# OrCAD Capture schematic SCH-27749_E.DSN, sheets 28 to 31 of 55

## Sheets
28 T4240 DDR Controller #1: size C
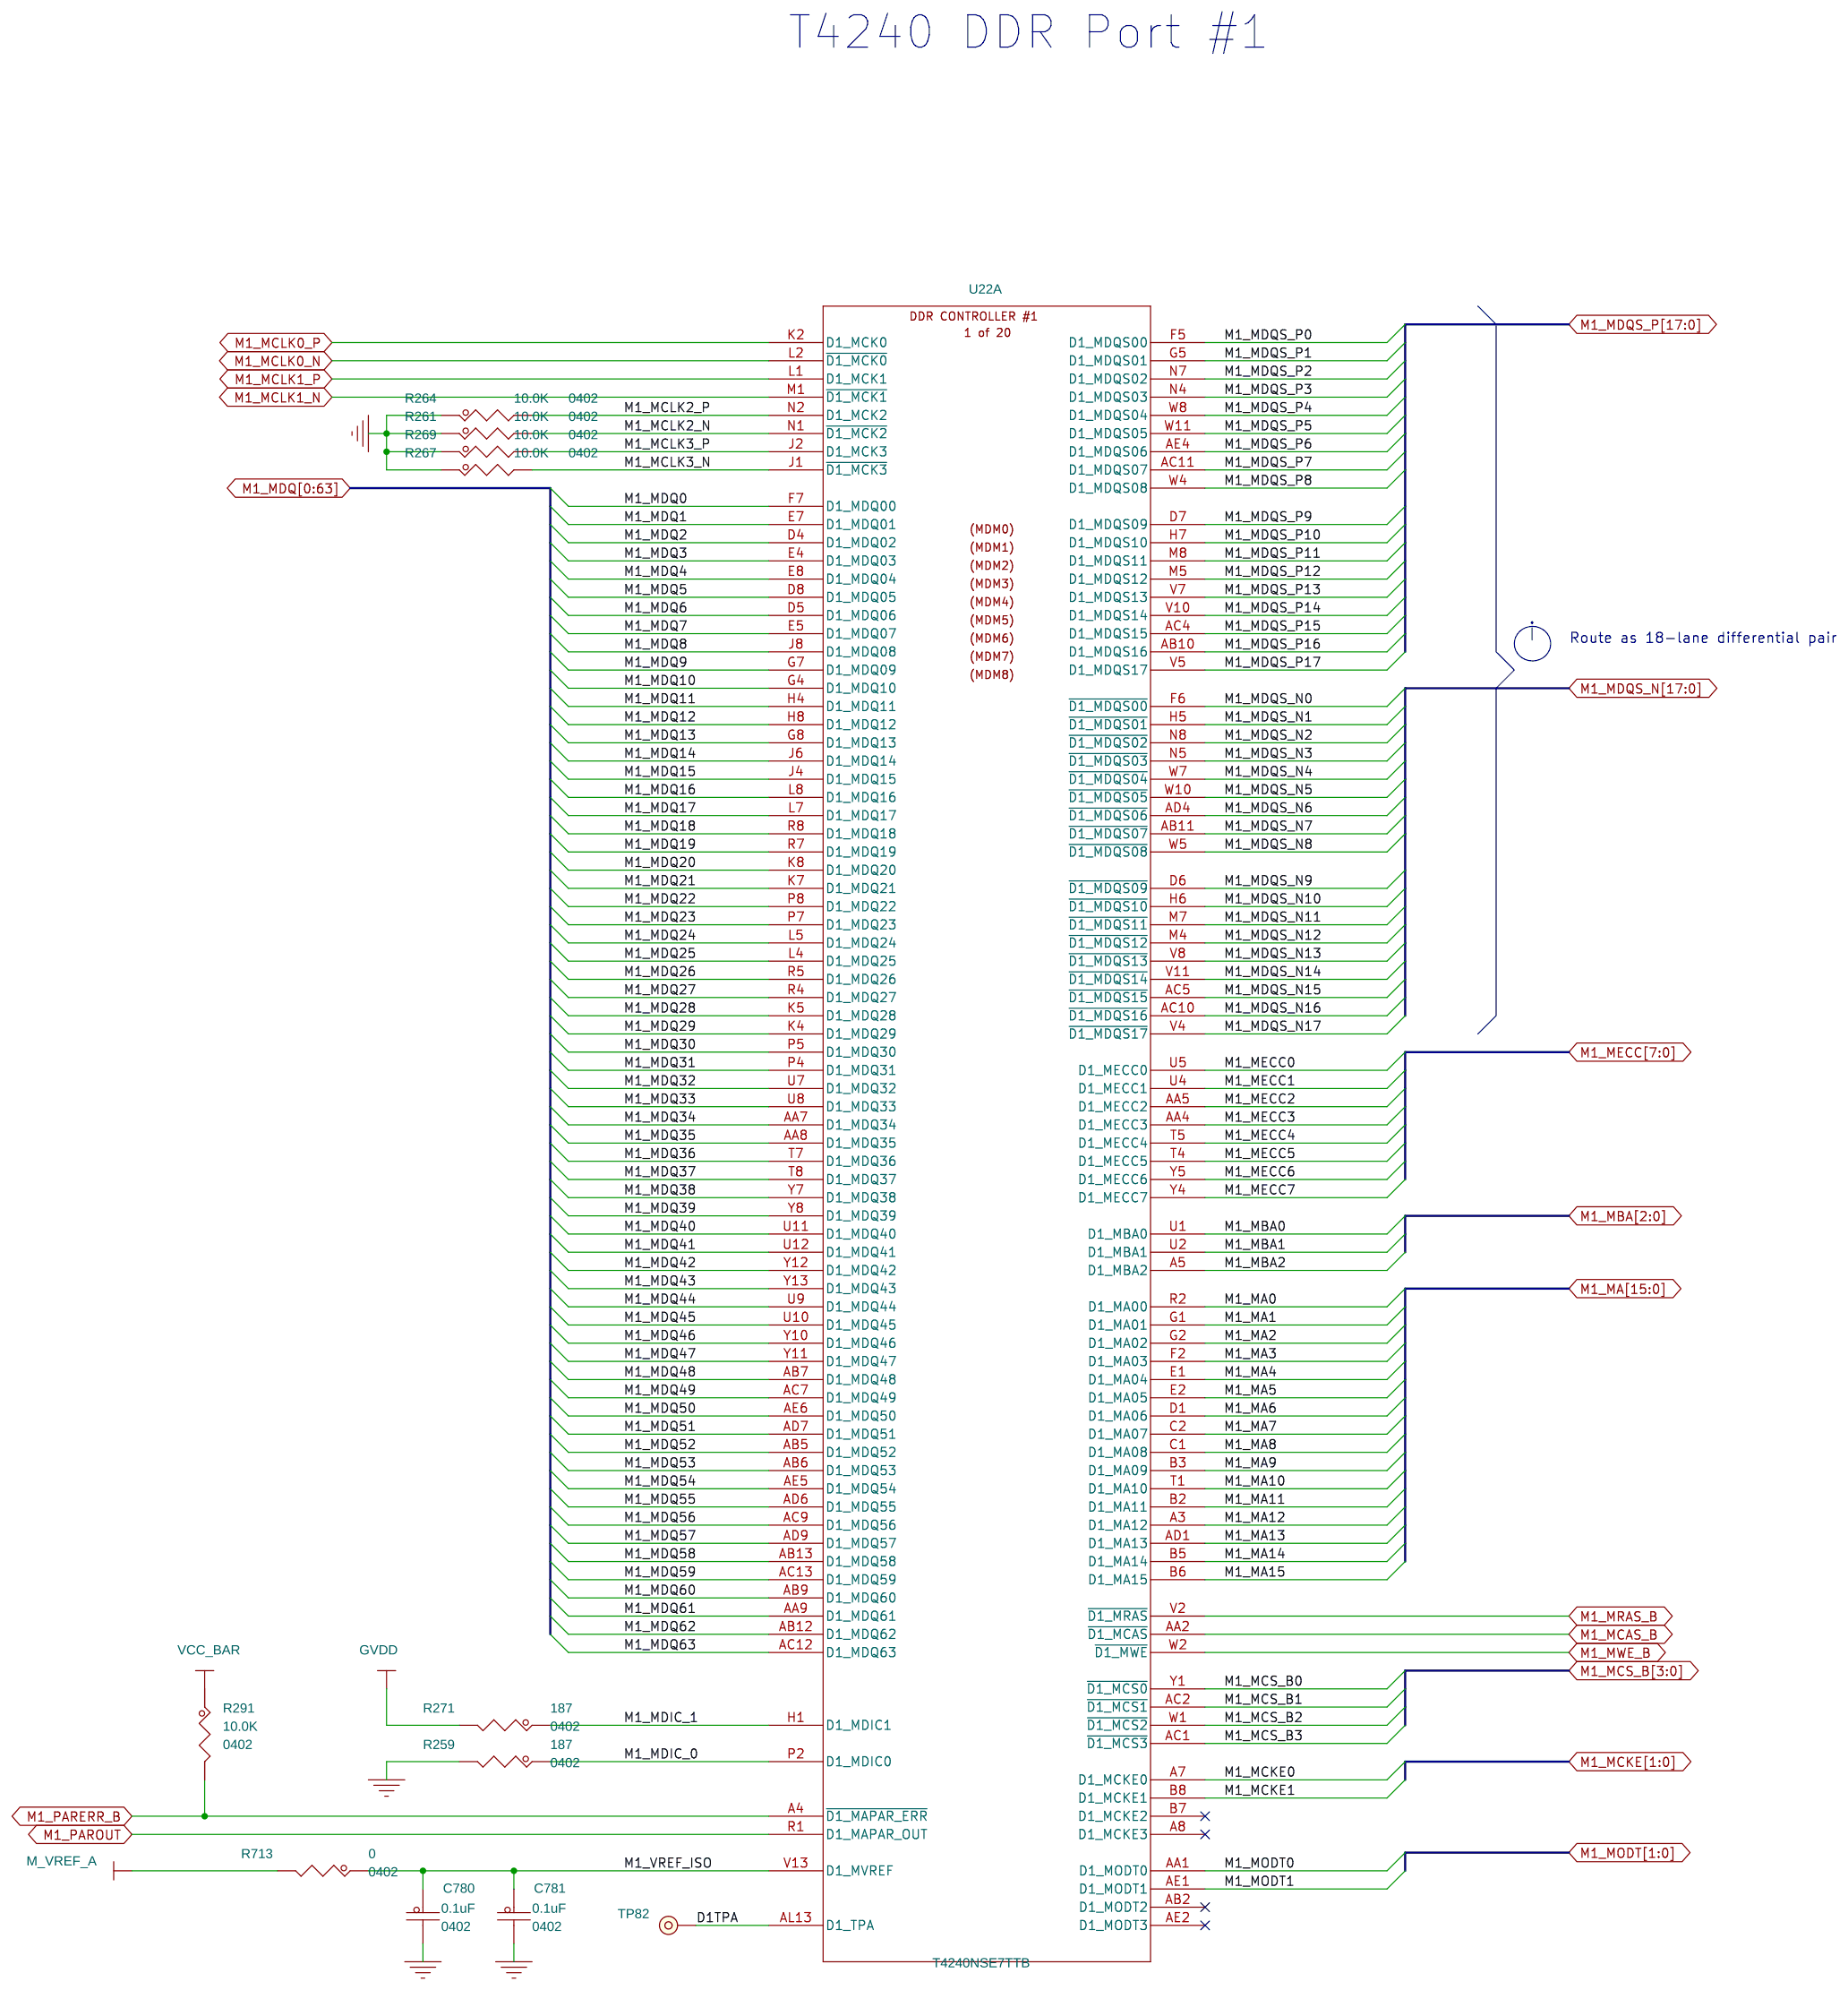
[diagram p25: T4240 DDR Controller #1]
29 T4240 DDR Controller #2: size C
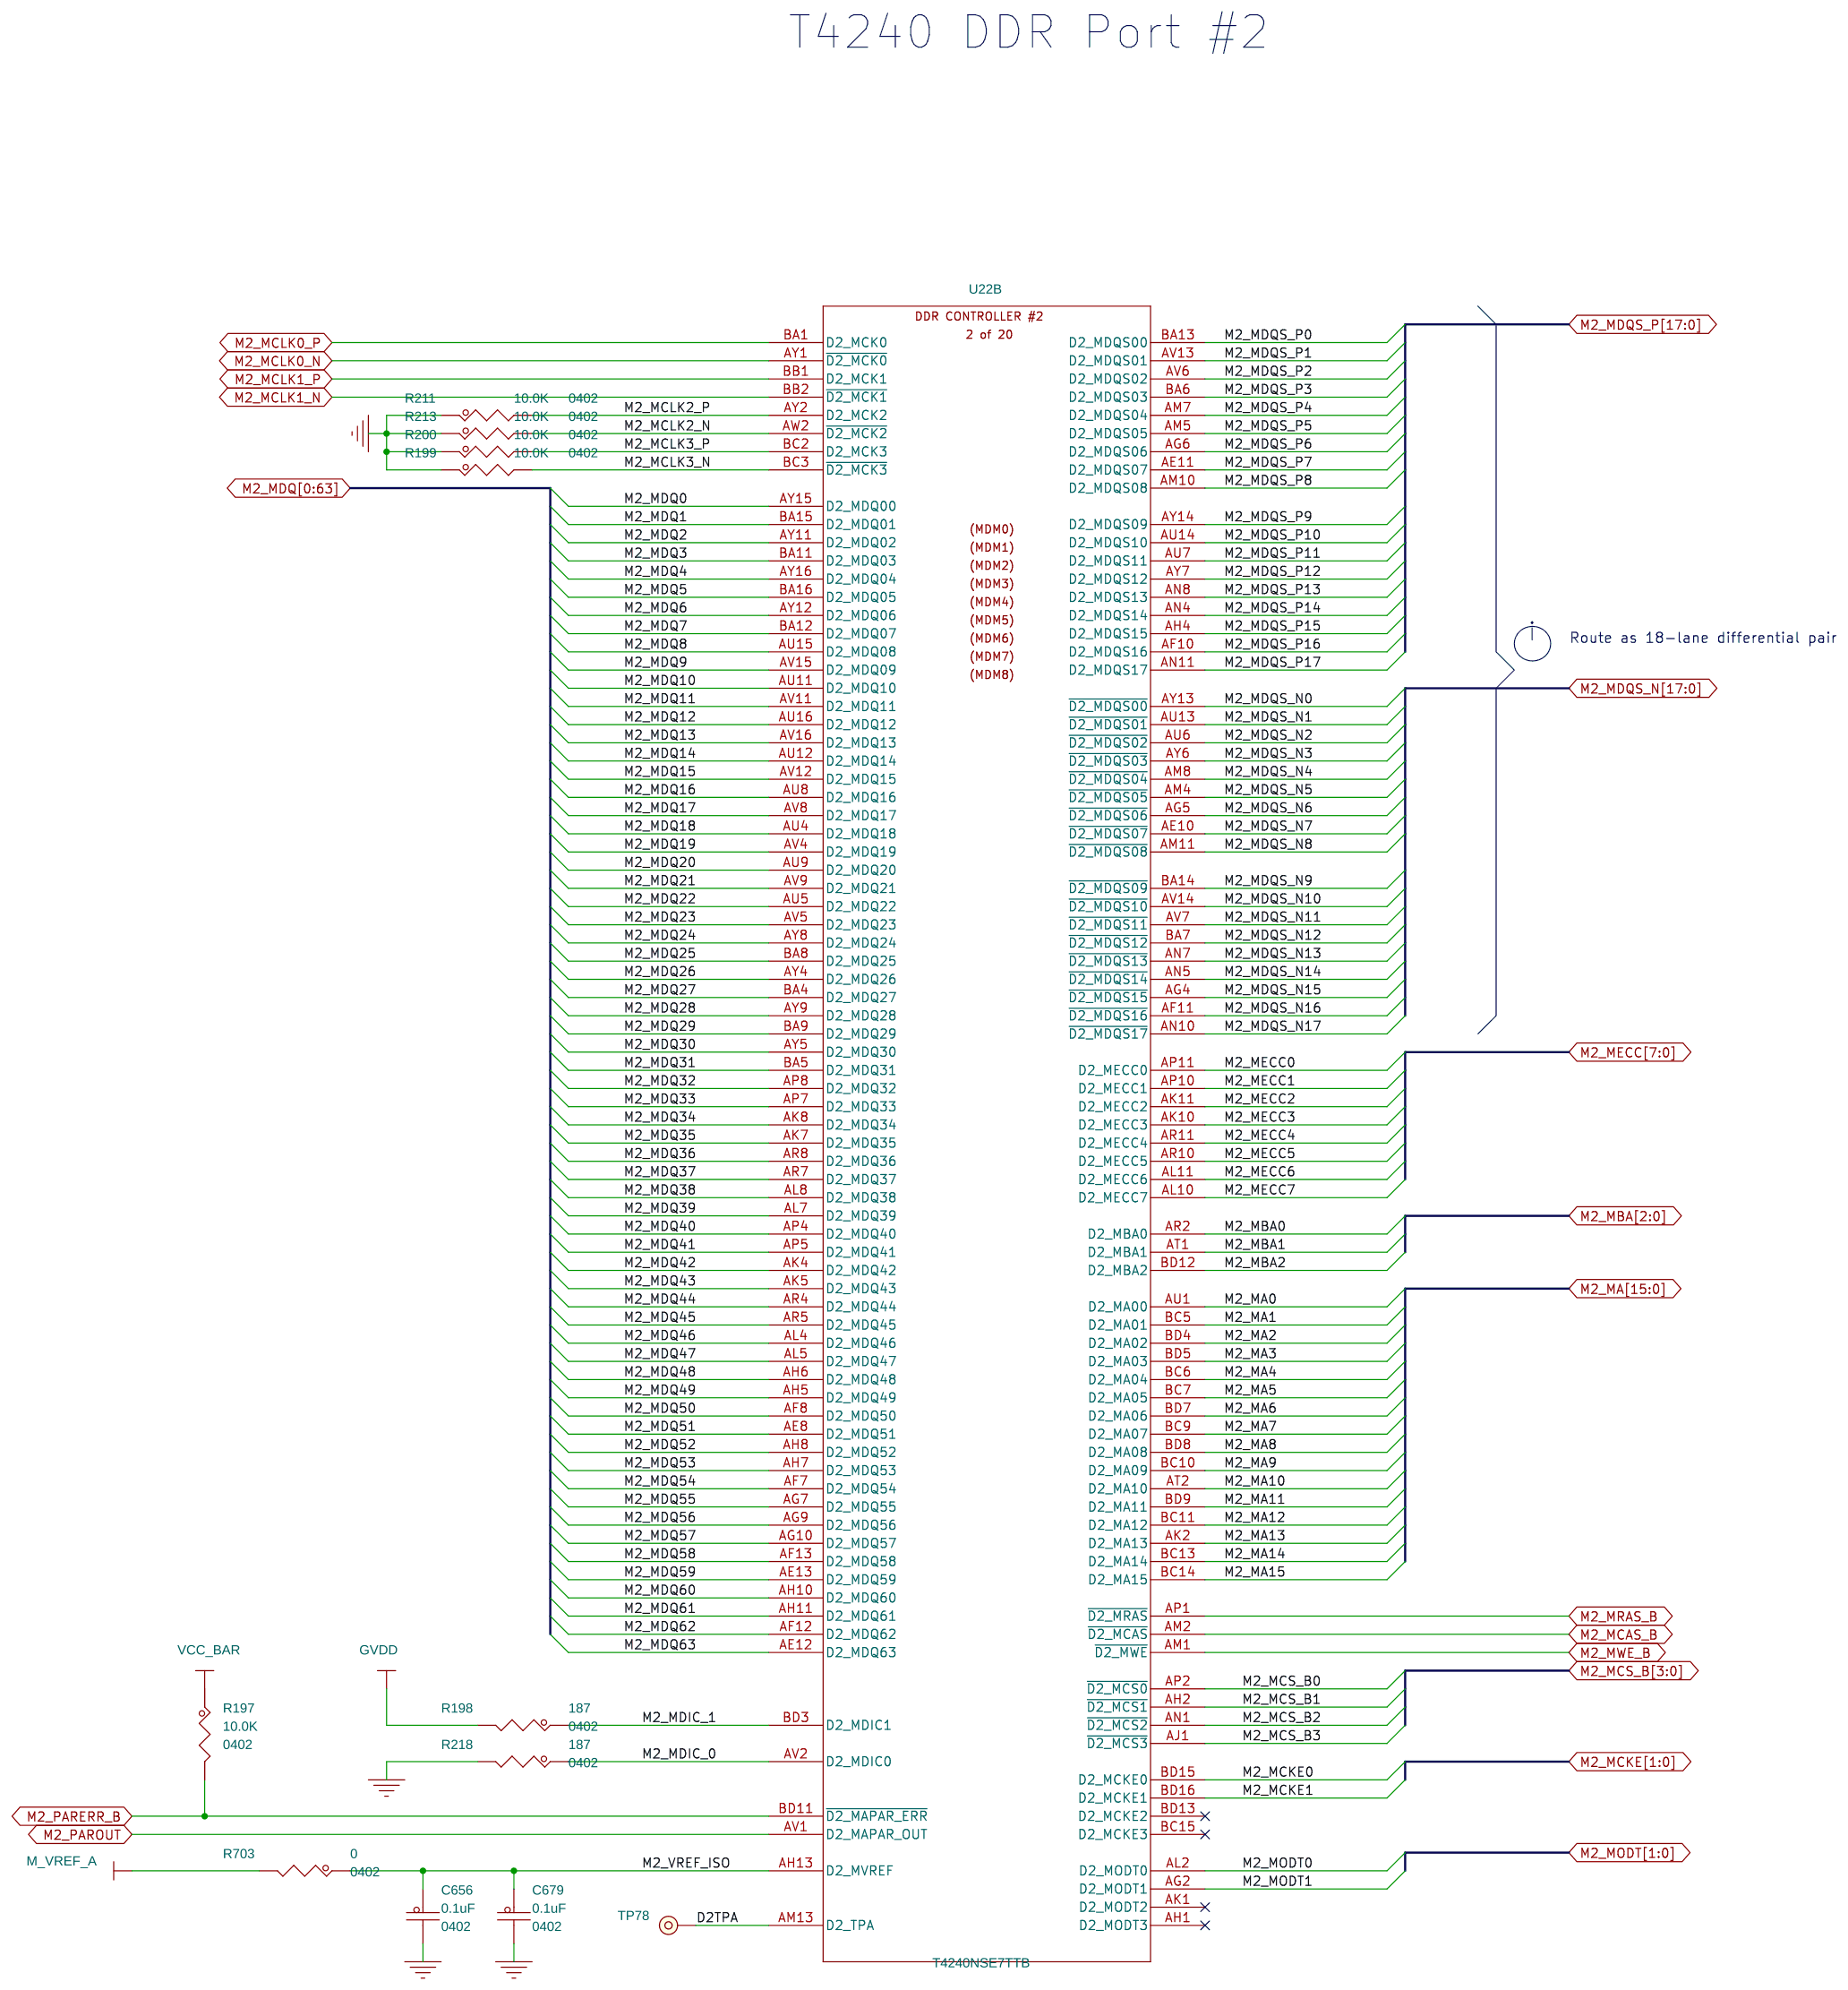
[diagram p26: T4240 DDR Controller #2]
30 T4240 DDR Controller #3: size C
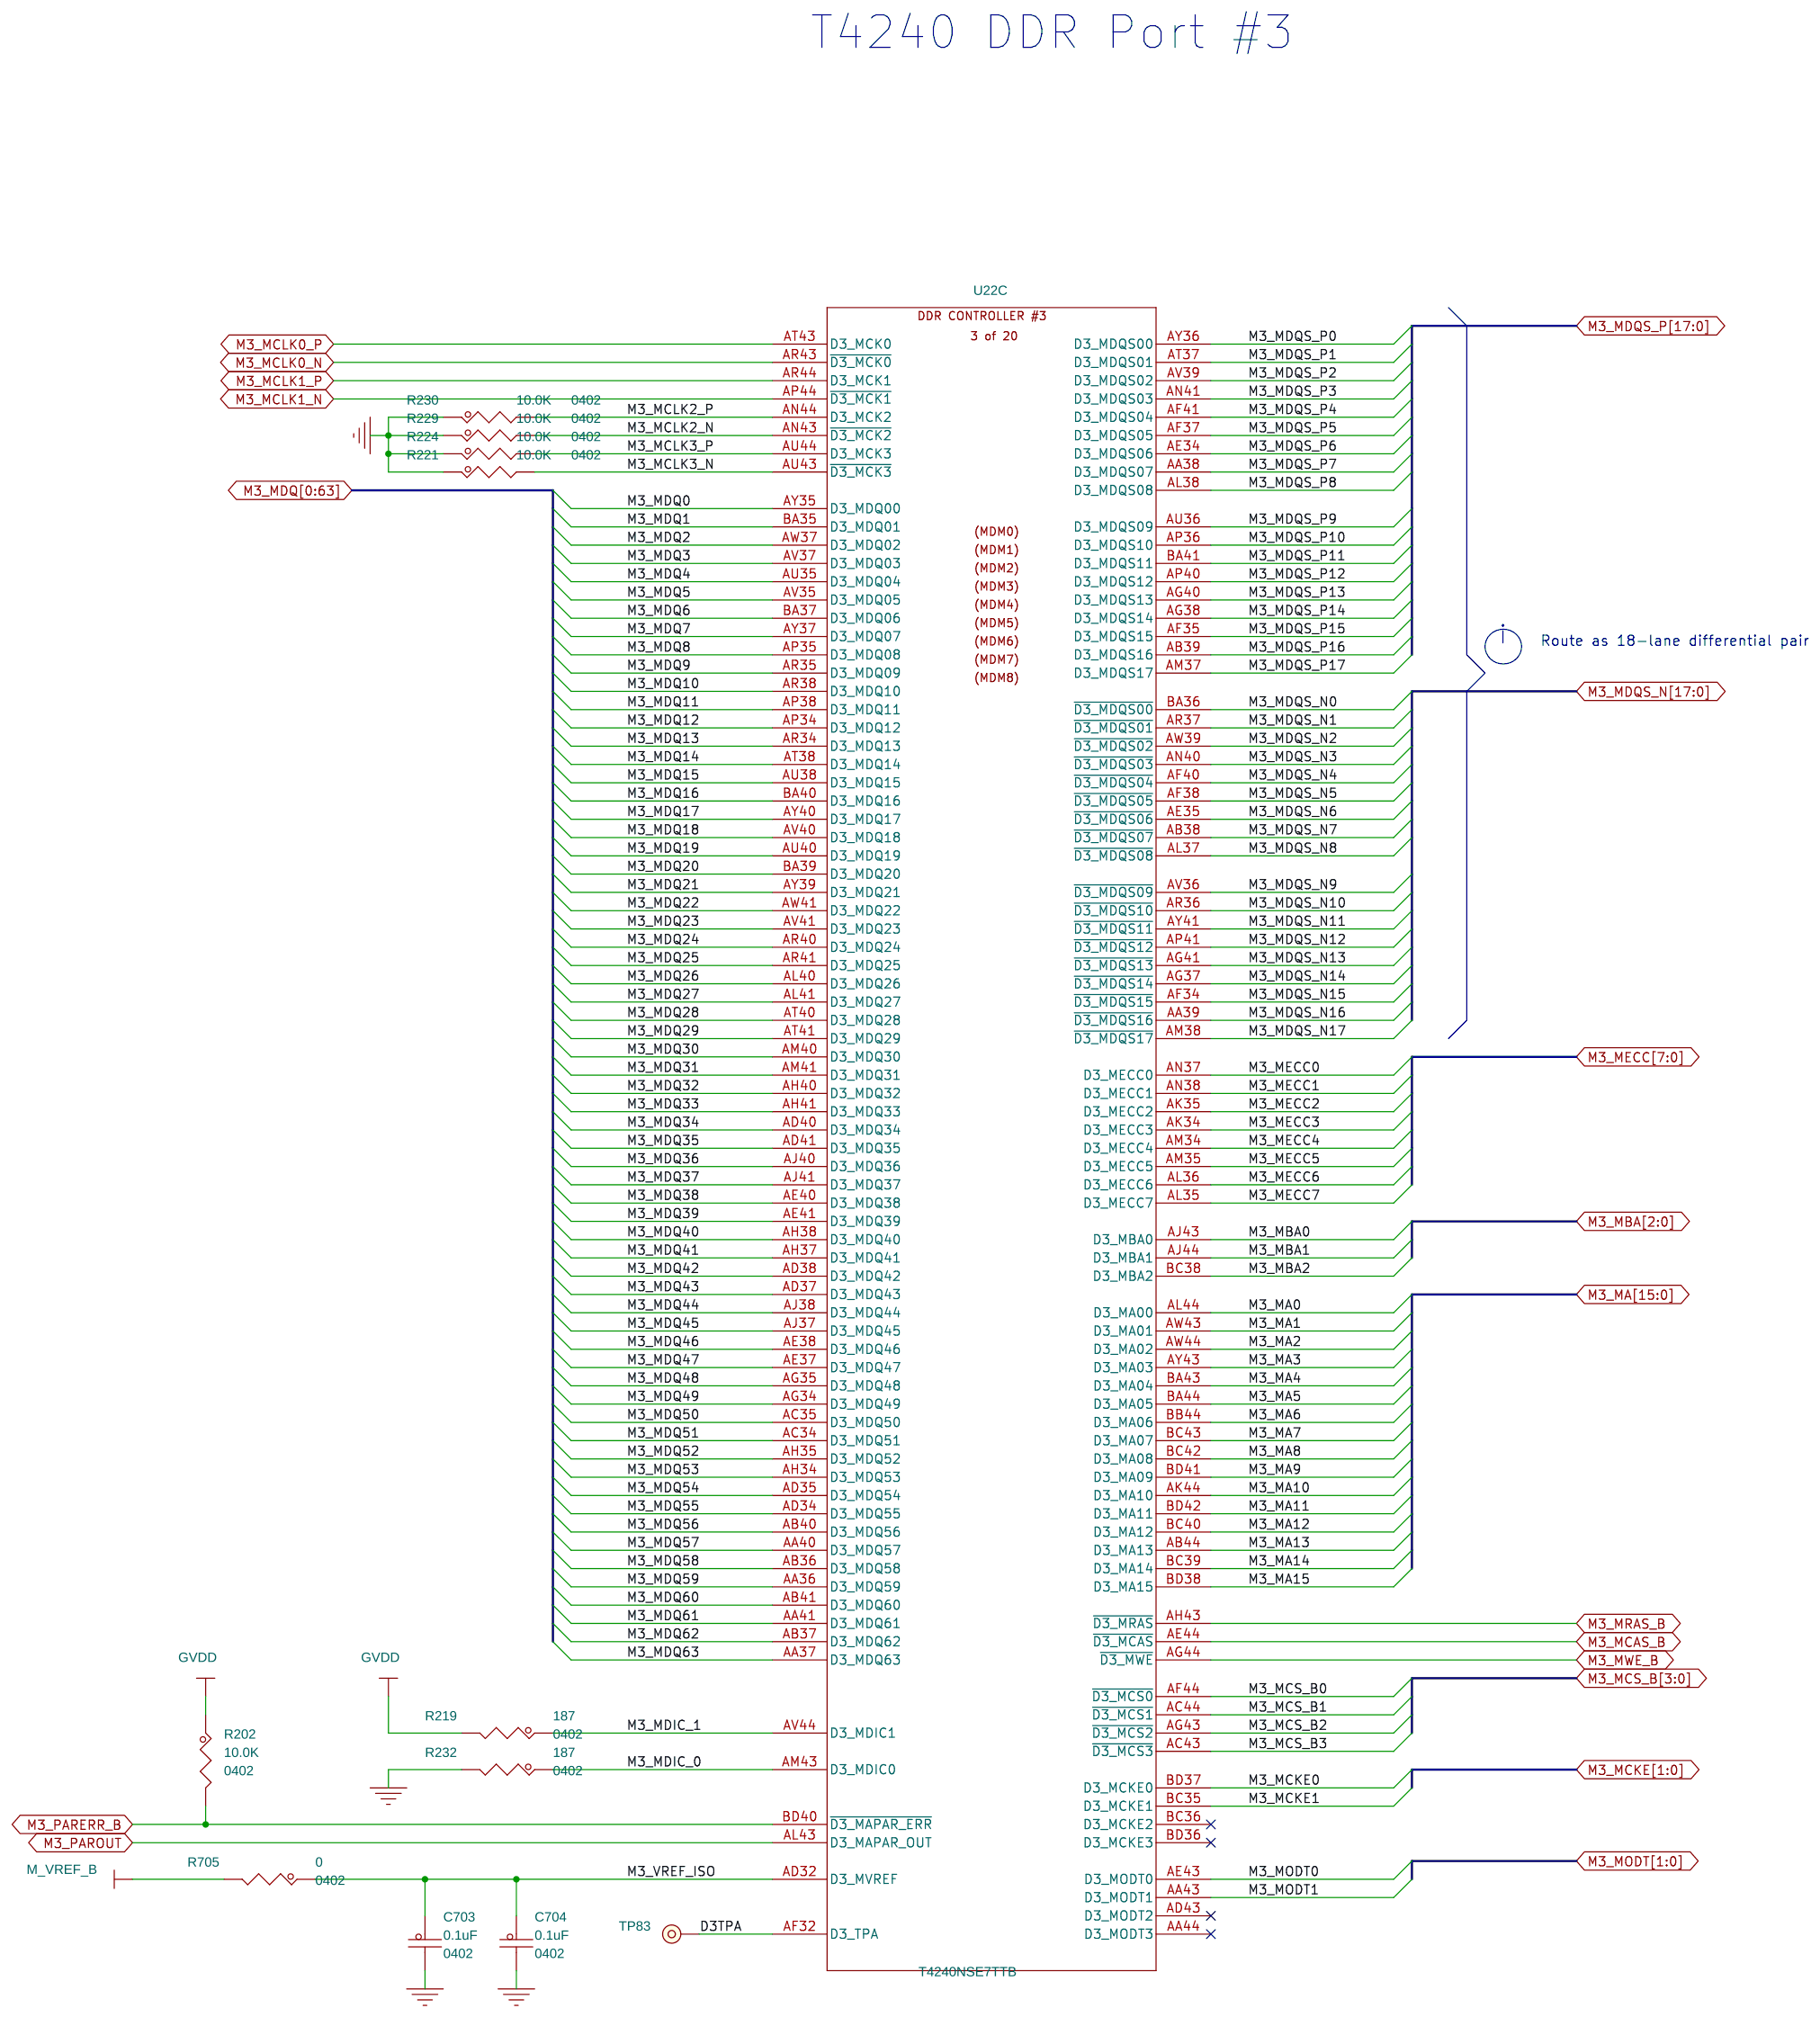
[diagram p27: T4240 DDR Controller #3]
31 DDR #1 DIMM: size C
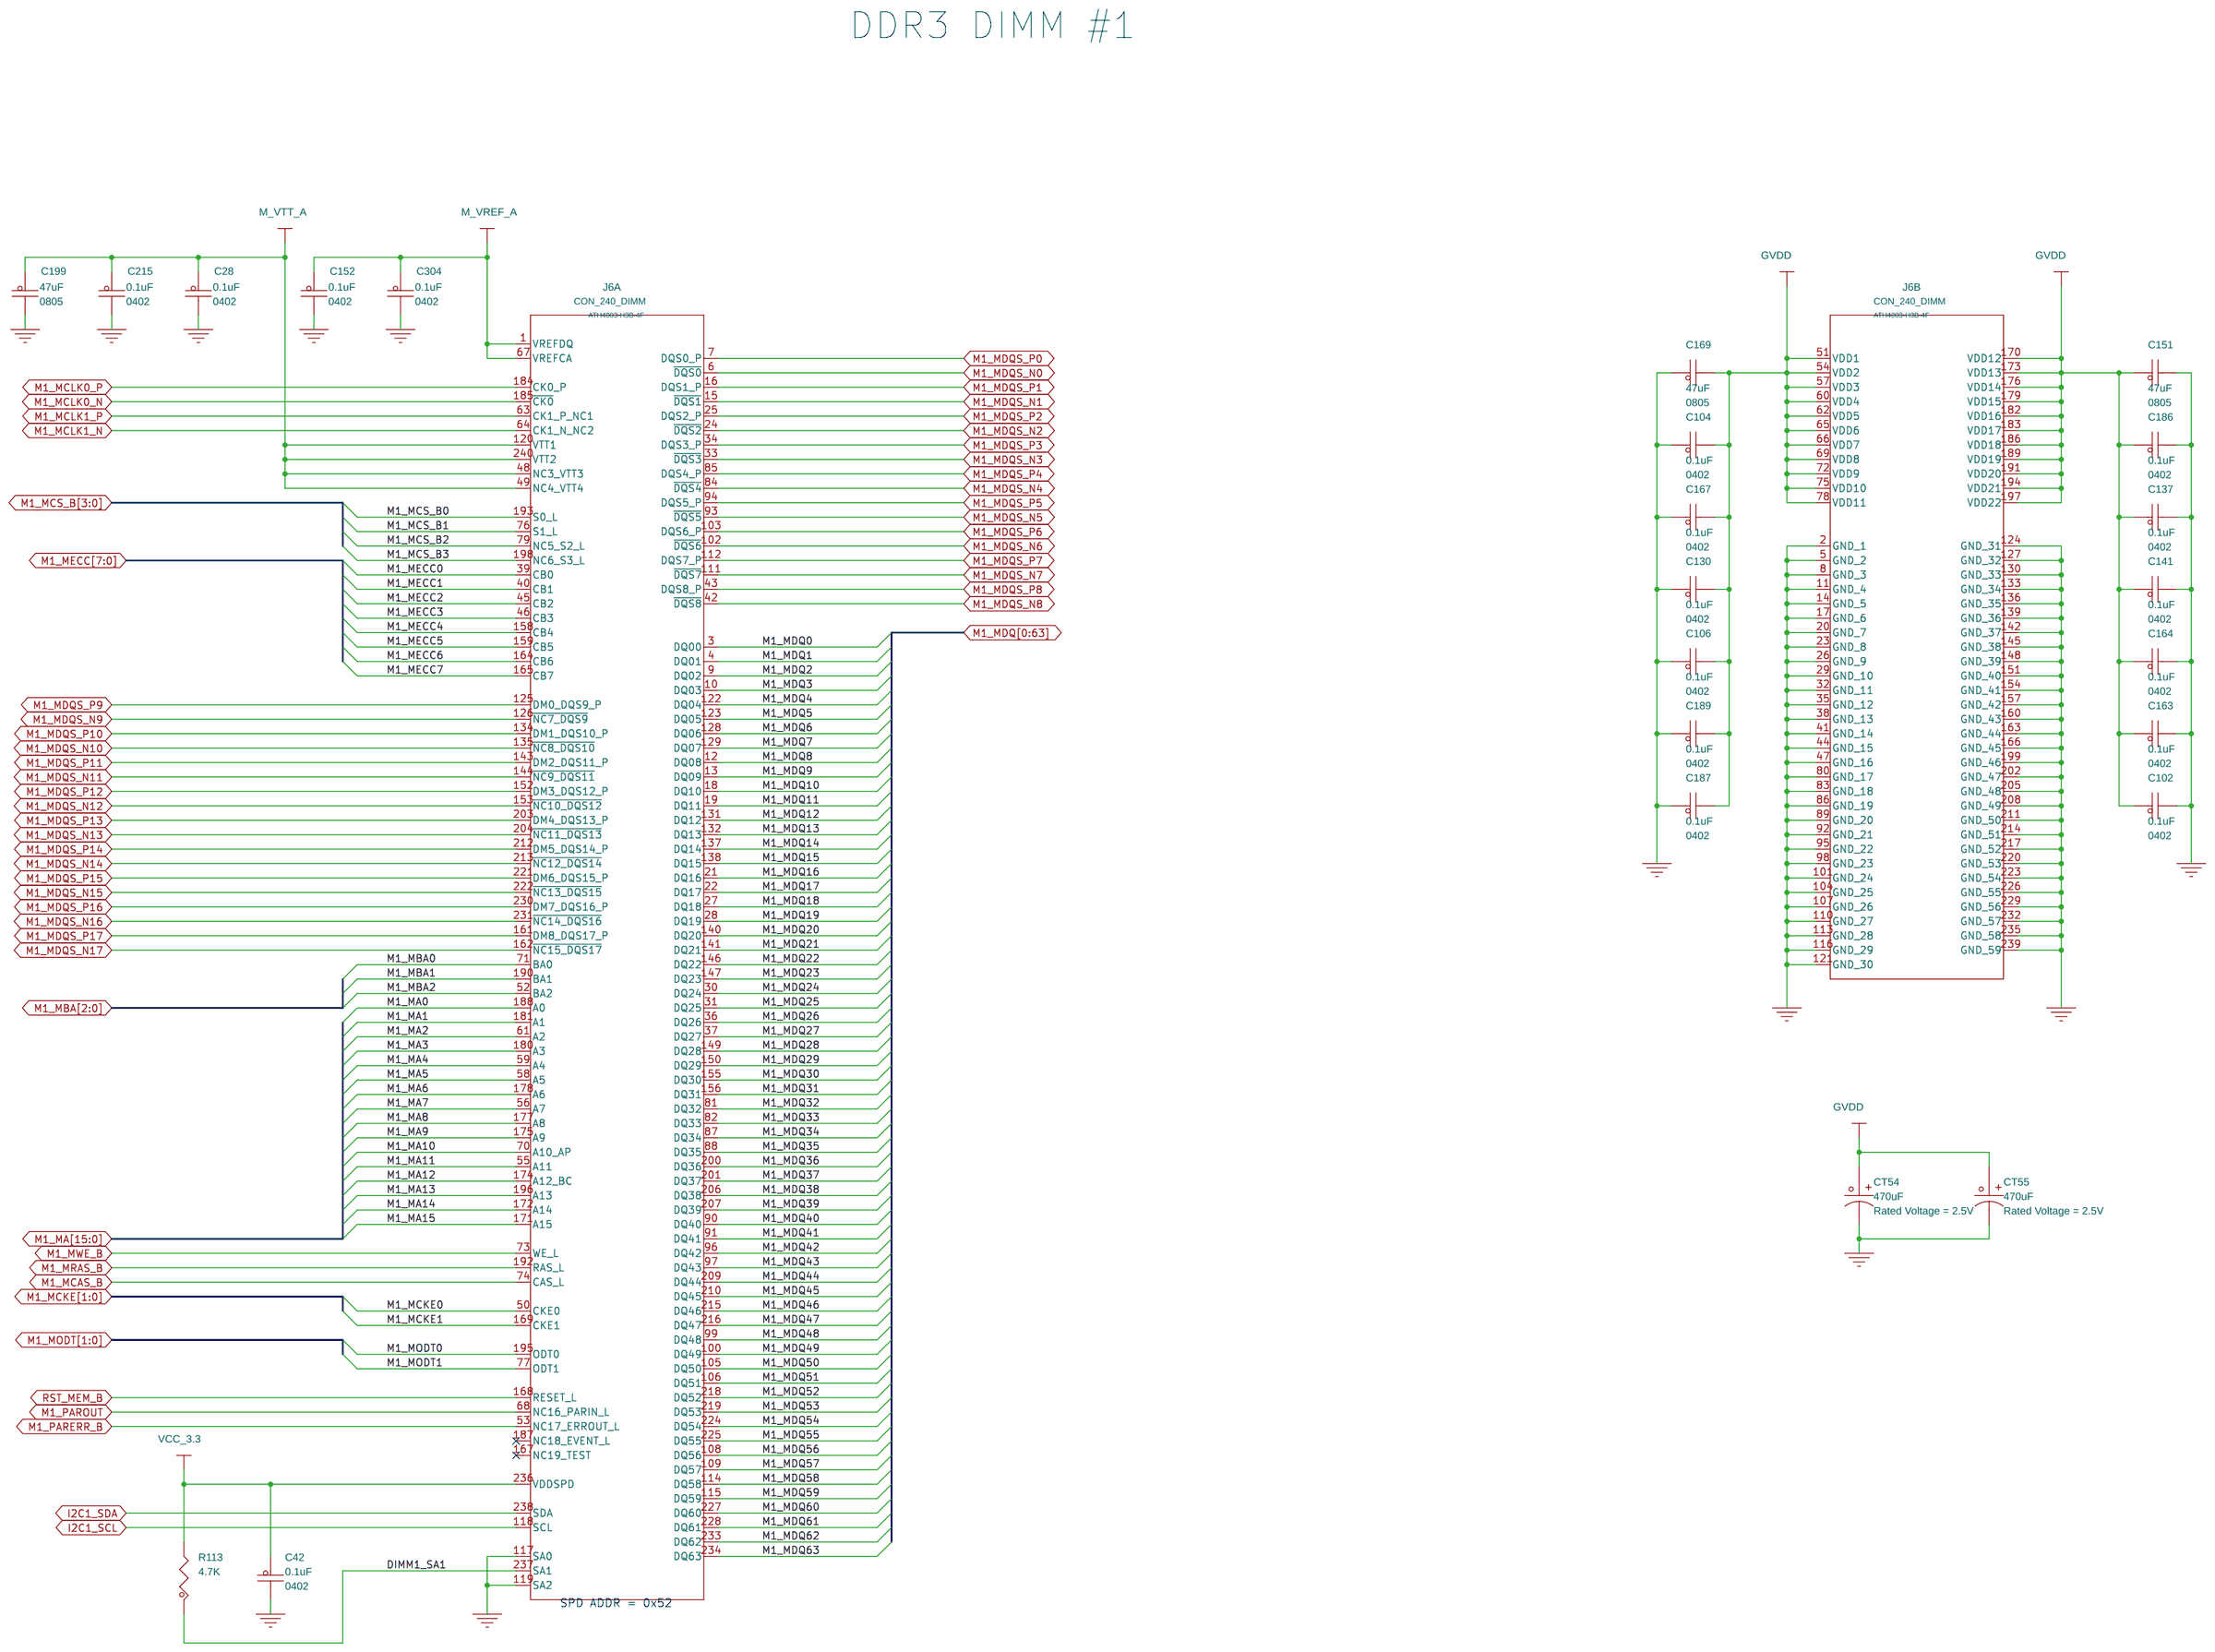
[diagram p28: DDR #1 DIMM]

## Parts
sheet DDR #1 DIMM
C28  0.1uF  [CC0402_HD]
C42  0.1uF  [CC0402_HD]
C102  0.1uF  [CC0402_HD]
C104  0.1uF  [CC0402_HD]
C106  0.1uF  [CC0402_HD]
C130  0.1uF  [CC0402_HD]
C137  0.1uF  [CC0402_HD]
C141  0.1uF  [CC0402_HD]
C151  47uF  [CC0805_OV]
C152  0.1uF  [CC0402_HD]
C163  0.1uF  [CC0402_HD]
C164  0.1uF  [CC0402_HD]
C167  0.1uF  [CC0402_HD]
C169  47uF  [CC0805_OV]
C186  0.1uF  [CC0402_HD]
C187  0.1uF  [CC0402_HD]
C189  0.1uF  [CC0402_HD]
C199  47uF  [CC0805_OV]
C215  0.1uF  [CC0402_HD]
C304  0.1uF  [CC0402_HD]
CT54  470uF  [CC7343A]
CT55  470uF  [CC7343A]
J6  CON_240_DIMM  [CON_240_DDR3_DIMM_SKT]  (sections A,B)
R113  4.7K  [RC0402_25]
sheet T4240 DDR Controller #1
C780  0.1uF  [CC0402_HD]
C781  0.1uF  [CC0402_HD]
R259  187  [RC0402_25]
R261  10.0K  [RC0402_25]
R264  10.0K  [RC0402_25]
R267  10.0K  [RC0402_25]
R269  10.0K  [RC0402_25]
R271  187  [RC0402_25]
R291  10.0K  [RC0402_25]
R713  0  [RC0402_25]
TP82  TPAD_020  [tpad_020_top]
sheet T4240 DDR Controller #2
C656  0.1uF  [CC0402_HD]
C679  0.1uF  [CC0402_HD]
R197  10.0K  [RC0402_25]
R198  187  [RC0402_25]
R199  10.0K  [RC0402_25]
R200  10.0K  [RC0402_25]
R211  10.0K  [RC0402_25]
R213  10.0K  [RC0402_25]
R218  187  [RC0402_25]
R703  0  [RC0402_25]
TP78  TPAD_020  [tpad_020_top]
U22  T4240NSE7TTB  [BGA1932_1MM_45X45MM]  (sections A,B,C,D,E,F,G,H,I,J,K,L,M,N,O,P,Q,R,S,T)
sheet T4240 DDR Controller #3
C703  0.1uF  [CC0402_HD]
C704  0.1uF  [CC0402_HD]
R202  10.0K  [RC0402_25]
R219  187  [RC0402_25]
R221  10.0K  [RC0402_25]
R224  10.0K  [RC0402_25]
R229  10.0K  [RC0402_25]
R230  10.0K  [RC0402_25]
R232  187  [RC0402_25]
R705  0  [RC0402_25]
TP83  TPAD_020  [tpad_020_top]

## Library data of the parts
C28 C42 C102 C104 C106 C130 C137 C141 C152 C163 C164 C167 C186 C187 C189 C215 C304 C656 C679 C703 C704 C780 C781 = CAP_NP: CAP CER 0.1uF 16V 10% X7R AEC-Q200 0402; AGILE_PN: 150-79025; CAD_APPROVED: Yes; FPLIST: CC0402_25,CC0402_HD,0402_CC,capc0402_l; HEIGHT: 0.55MM; MFG_NAME01: MURATA; MFG_PN01: GCM155R71C104KA55D; Package: 0402; Package Size: 0402; Package Type: ø180mm Reel PAPER; Part Number: 4CC104B163X00; Product Name: (H)MLCC 0.1uF/16V +-10% 0402 X7R; ROHS: Yes; Rated Voltage: 16V; Temp Range: -55C to +125C; Tolerance: 10%
C151 C169 C199 = CAP_NP: CAP CER 47uF 6.3V 20% X5R AEC-Q200 0805; AGILE_PN: 150-80462; CAD_APPROVED: Yes; FPLIST: CC0805_OV,CC0805,0805_CC; HEIGHT: 1.45MM; MFG_NAME01: MURATA; MFG_PN01: GRT21BR60J476ME13L; Package: 0805; Package Size: 2x1.25MM; Package Type: 0805; Part Number: 4CC476D631X00; Product Name: (H)MLCC 47uF/6.3V +-20% 0805 X5R; ROHS: Yes; Rated Voltage: 6.3V; Temp Range: -55C to +85C; Tolerance: 20%
CT54 CT55 = CAP_POL: CAP TANT ESR=0.009 OHMS 470UF 2.5V 20% -- 7343-18; AGILE_PN: 150-78476; CAD_APPROVED: Yes; HEIGHT: 1.9MM; MFG_NAME01: SANYO; MFG_PN01: 2R5TPE470M9; Package: SMD; Part Number: 4CP477D021X00; Product Name: KO CAP 470uF/2.5V KEMET:T520V477M2R5ATE009; ROHS: Yes; Rated Voltage: 2.5V; Tolerance: 20%
J6 = DDR3_240P: CON 240 DIMM DDR3 1.5V SKT TH 1MM SP 910H .125 THK PCB AU 125L; AGILE_PN: 210-77672; CAD_APPROVED: Yes; CDS_LIB: fcl_connector; COMP_HEIGHT: 23.10 MM; CPN: TMP-WF-6058; CaptureCellPackProp: DDR3_240PA; DRAWING: @EXPEDITION_LIB.EXPEDITION(SCH_1):PAGE33; GROUP: DIMM2; HEIGHT: 23.10 MM; LOCATION: J22; MFG_NAME: FOXCONN; MFG_NAME01: FOXCONN; MFG_PN: ATH4003-H3B-4F; MFG_PN01: ATH4003-H3B-4F; PHYS_PAGE: 33; Part Number: 4SRD324006X00; Product Name: DDR3 DIMM SOCKET 240PIN FOXCONN:ATH4017-P3B-4F; ROHS: Yes; ROT: 0; XY: (-5700,2625)
R113 = RES: RES MF 4.7K 1/10W 5% AEC-Q200 0402; AGILE_PN: 470-82064; CAD_APPROVED: Yes; FPLIST: RC0402_25,RC0402_HD,0402_CC,RC0402_X2; HEIGHT: 0.41mm; MFG_NAME01: KOA SPEER; MFG_PN01: RK73B1ETTP472J; ROHS: Yes; Temp Range: -55C to +155C; Tolerance: 5%
R198 R218 R219 R232 R259 R271 = RES: RES MF 187 OHM 1/10W 1% AEC-Q200 0402; AGILE_PN: 470-30767; CAD_APPROVED: Yes; FPLIST: RC0402_25,RC0402_HD,0402_CC; HEIGHT: 0.40 MM; MFG_NAME01: KOA SPEER; MFG_PN01: RK73H1ETTP1870F; Package: 0402; Part Number: 4RC1871B11X00; Product Name: (H)RES 187E 1/16W 0402 1% PBFREE; ROHS: Yes; Temp Range: -55C to +155C; Tolerance: 1%
R197 R199 R200 R202 R211 R213 R221 R224 R229 R230 R261 R264 R267 R269 R291 = RES: RES MF 10.0K 1/16W 1% AEC-Q200 0402; AGILE_PN: 470-75416; CAD_APPROVED: Yes; FPLIST: RC0402_25,RC0402_HD,0402_CC; HEIGHT: 0.4MM; MFG_NAME01: KOA SPEER; MFG_PN01: RK73H1ETTP1002F; Package: 0402; Part Number: 4RC1003B11X00; Product Name: (H)RES 10K 1/16W 0402 1% PBFREE; ROHS: Yes; Temp Range: –55 °C to +155 °C; Tolerance: 1%
R703 R705 R713 = RES: RES MF ZERO OHM 1/10W -- 0402; AGILE_PN: 470-79965; CAD_APPROVED: Yes; FPLIST: RC0402_25,RC0402_HD,RC0402_X2,0402_CC,RC0402_X3; HEIGHT: 0.4MM; MFG_NAME01: PANASONIC; MFG_PN01: ERJ-2GE0R00X; Package: 0402; Part Number: 4RC0000B51X00; Product Name: (H)RES 0E 1/16W 0402 5% PBFREE; ROHS: Yes; Temp Range: –55 °C to +155 °C
TP78 TP82 TP83 = T_POINT_TH: TEST POINT PAD 20 MILS SMT, NOT PART TO ORDER; AGILE_PN: 211-81036; CAD_APPROVED: Yes; FPLIST: tpad_020_top,tpad_020_btm_nsp; HEIGHT: 0.127MM; MFG_NAME01: NO PART ORDER; MFG_PN01: NA; ROHS: Yes
U22 = T4240: IC MPU 64BIT T4240 1.8GHz 1.025V CRYPTO QorIQ PBGA1932; 3D_Mechanical_Footprint_File: http://fcl.am.freescale.net/ALLEGRO/step/bga1932_1mm_45x45mm.STEP; AGILE_PN: 330-77243; CAD_APPROVED: Yes; HEIGHT: 3.33 MM; MFG_NAME01: NXP SEMICONDUCTOR; Package Size: SOT1645-1; Part Number: 71F101G206X01; Product Name: (N)SOC FREESCALE:T4240NSE7TTB; ROHS: Yes; Temp Range: 0 to 105 °C

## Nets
GND: C28.2 C42.2 C102.2 C104.1 C106.1 C130.1 C137.2 C141.2 C151.2 C152.2 C163.2 C164.2 C167.1 C169.1 C186.2 C187.1 C189.1 C199.2 C215.2 C304.2 C656.2 C679.2 C703.2 C704.2 C780.2 C781.2 CT54.2 CT55.2 J6.2(GND_1) J6.5(GND_2) J6.8(GND_3) J6.11(GND_4) J6.14(GND_5) J6.17(GND_6) J6.20(GND_7) J6.23(GND_8) J6.26(GND_9) J6.29(GND_10) J6.32(GND_11) J6.35(GND_12) J6.38(GND_13) J6.41(GND_14) J6.44(GND_15) J6.47(GND_16) J6.80(GND_17) J6.83(GND_18) J6.86(GND_19) J6.89(GND_20) J6.92(GND_21) J6.95(GND_22) J6.98(GND_23) J6.101(GND_24) J6.104(GND_25) J6.107(GND_26) J6.110(GND_27) J6.113(GND_28) J6.116(GND_29) J6.117(SA0) J6.119(SA2) J6.121(GND_30) J6.124(GND_31) J6.127(GND_32) J6.130(GND_33) J6.133(GND_34) J6.136(GND_35) J6.139(GND_36) J6.142(GND_37) J6.145(GND_38) J6.148(GND_39) J6.151(GND_40) J6.154(GND_41) J6.157(GND_42) J6.160(GND_43) J6.163(GND_44) J6.166(GND_45) J6.199(GND_46) J6.202(GND_47) J6.205(GND_48) J6.208(GND_49) J6.211(GND_50) J6.214(GND_51) J6.217(GND_52) J6.220(GND_53) J6.223(GND_54) J6.226(GND_55) J6.229(GND_56) J6.232(GND_57) J6.235(GND_58) J6.239(GND_59) R199.1 R200.1 R211.1 R213.1 R218.2 R221.1 R224.1 R229.1 R230.1 R232.2 R259.2 R261.1 R264.1 R267.1 R269.1 ; also on sheet 6 7 8 9 10 11 12 13 14 15 16 18 19 20 21 22 24 25 27 32 33 34 35 36 37 38 39 40 41 42 43 44 45 46 47 48 49 50 51 52 53 54
VCC_3.3: C42.1 J6.236(VDDSPD) R113.2 ; also on sheet 6 12 13 16 18 24 25 32 33 36 39 40 41 42 43 44 47 48 49 50 51 53
D1TPA: TP82.1(TP) U22.AL13(D1_TPA)
D2TPA: TP78.1(TP) U22.AM13(D2_TPA)
D3TPA: TP83.1(TP) U22.AF32(D3_TPA)
DIMM1_SA1: J6.237(SA1) R113.1
GVDD: C102.1 C104.2 C106.2 C130.2 C137.1 C141.1 C151.1 C163.1 C164.1 C167.2 C169.2 C186.1 C187.2 C189.2 CT54.1 CT55.1 J6.51(VDD1) J6.54(VDD2) J6.57(VDD3) J6.60(VDD4) J6.62(VDD5) J6.65(VDD6) J6.66(VDD7) J6.69(VDD8) J6.72(VDD9) J6.75(VDD10) J6.78(VDD11) J6.170(VDD12) J6.173(VDD13) J6.176(VDD14) J6.179(VDD15) J6.182(VDD16) J6.183(VDD17) J6.186(VDD18) J6.189(VDD19) J6.191(VDD20) J6.194(VDD21) J6.197(VDD22) R197.1 R198.2 R202.1 R219.2 R271.2 R291.1 ; also on sheet 11 13 20 32 33
I2C1_SCL: J6.118(SCL) ; also on sheet 8 12 24 32 33 50 51 53
I2C1_SDA: J6.238(SDA) ; also on sheet 8 12 24 32 33 50 51 53
M1_MA0: J6.188(A0) U22.R2(D1_MA00)
M1_MA1: J6.181(A1) U22.G1(D1_MA01)
M1_MA2: J6.61(A2) U22.G2(D1_MA02)
M1_MA3: J6.180(A3) U22.F2(D1_MA03)
M1_MA4: J6.59(A4) U22.E1(D1_MA04)
M1_MA5: J6.58(A5) U22.E2(D1_MA05)
M1_MA6: J6.178(A6) U22.D1(D1_MA06)
M1_MA7: J6.56(A7) U22.C2(D1_MA07)
M1_MA8: J6.177(A8) U22.C1(D1_MA08)
M1_MA9: J6.175(A9) U22.B3(D1_MA09)
M1_MA10: J6.70(A10_AP) U22.T1(D1_MA10)
M1_MA11: J6.55(A11) U22.B2(D1_MA11)
M1_MA12: J6.174(A12_BC) U22.A3(D1_MA12)
M1_MA13: J6.196(A13) U22.AD1(D1_MA13)
M1_MA14: J6.172(A14) U22.B5(D1_MA14)
M1_MA15: J6.171(A15) U22.B6(D1_MA15)
M1_MBA0: J6.71(BA0) U22.U1(D1_MBA0)
M1_MBA1: J6.190(BA1) U22.U2(D1_MBA1)
M1_MBA2: J6.52(BA2) U22.A5(D1_MBA2)
M1_MCAS_B: J6.74(CAS_L) U22.AA2(~{D1_MCAS})
M1_MCKE0: J6.50(CKE0) U22.A7(D1_MCKE0)
M1_MCKE1: J6.169(CKE1) U22.B8(D1_MCKE1)
M1_MCLK0_N: J6.185(~{CK0}) U22.L2(~{D1_MCK0})
M1_MCLK0_P: J6.184(CK0_P) U22.K2(D1_MCK0)
M1_MCLK1_N: J6.64(CK1_N_NC2) U22.M1(~{D1_MCK1})
M1_MCLK1_P: J6.63(CK1_P_NC1) U22.L1(D1_MCK1)
M1_MCLK2_N: R261.2 U22.N1(~{D1_MCK2})
M1_MCLK2_P: R264.2 U22.N2(D1_MCK2)
M1_MCLK3_N: R267.2 U22.J1(~{D1_MCK3})
M1_MCLK3_P: R269.2 U22.J2(D1_MCK3)
M1_MCS_B0: J6.193(S0_L) U22.Y1(~{D1_MCS0})
M1_MCS_B1: J6.76(S1_L) U22.AC2(~{D1_MCS1})
M1_MCS_B2: J6.79(NC5_S2_L) U22.W1(~{D1_MCS2})
M1_MCS_B3: J6.198(NC6_S3_L) U22.AC1(~{D1_MCS3})
M1_MDIC_0: R259.1 U22.P2(D1_MDIC0)
M1_MDIC_1: R271.1 U22.H1(D1_MDIC1)
M1_MDQ0: J6.3(DQ00) U22.F7(D1_MDQ00)
M1_MDQ1: J6.4(DQ01) U22.E7(D1_MDQ01)
M1_MDQ2: J6.9(DQ02) U22.D4(D1_MDQ02)
M1_MDQ3: J6.10(DQ03) U22.E4(D1_MDQ03)
M1_MDQ4: J6.122(DQ04) U22.E8(D1_MDQ04)
M1_MDQ5: J6.123(DQ05) U22.D8(D1_MDQ05)
M1_MDQ6: J6.128(DQ06) U22.D5(D1_MDQ06)
M1_MDQ7: J6.129(DQ07) U22.E5(D1_MDQ07)
M1_MDQ8: J6.12(DQ08) U22.J8(D1_MDQ08)
M1_MDQ9: J6.13(DQ09) U22.G7(D1_MDQ09)
M1_MDQ10: J6.18(DQ10) U22.G4(D1_MDQ10)
M1_MDQ11: J6.19(DQ11) U22.H4(D1_MDQ11)
M1_MDQ12: J6.131(DQ12) U22.H8(D1_MDQ12)
M1_MDQ13: J6.132(DQ13) U22.G8(D1_MDQ13)
M1_MDQ14: J6.137(DQ14) U22.J6(D1_MDQ14)
M1_MDQ15: J6.138(DQ15) U22.J4(D1_MDQ15)
M1_MDQ16: J6.21(DQ16) U22.L8(D1_MDQ16)
M1_MDQ17: J6.22(DQ17) U22.L7(D1_MDQ17)
M1_MDQ18: J6.27(DQ18) U22.R8(D1_MDQ18)
M1_MDQ19: J6.28(DQ19) U22.R7(D1_MDQ19)
M1_MDQ20: J6.140(DQ20) U22.K8(D1_MDQ20)
M1_MDQ21: J6.141(DQ21) U22.K7(D1_MDQ21)
M1_MDQ22: J6.146(DQ22) U22.P8(D1_MDQ22)
M1_MDQ23: J6.147(DQ23) U22.P7(D1_MDQ23)
M1_MDQ24: J6.30(DQ24) U22.L5(D1_MDQ24)
M1_MDQ25: J6.31(DQ25) U22.L4(D1_MDQ25)
M1_MDQ26: J6.36(DQ26) U22.R5(D1_MDQ26)
M1_MDQ27: J6.37(DQ27) U22.R4(D1_MDQ27)
M1_MDQ28: J6.149(DQ28) U22.K5(D1_MDQ28)
M1_MDQ29: J6.150(DQ29) U22.K4(D1_MDQ29)
M1_MDQ30: J6.155(DQ30) U22.P5(D1_MDQ30)
M1_MDQ31: J6.156(DQ31) U22.P4(D1_MDQ31)
M1_MDQ32: J6.81(DQ32) U22.U7(D1_MDQ32)
M1_MDQ33: J6.82(DQ33) U22.U8(D1_MDQ33)
M1_MDQ34: J6.87(DQ34) U22.AA7(D1_MDQ34)
M1_MDQ35: J6.88(DQ35) U22.AA8(D1_MDQ35)
M1_MDQ36: J6.200(DQ36) U22.T7(D1_MDQ36)
M1_MDQ37: J6.201(DQ37) U22.T8(D1_MDQ37)
M1_MDQ38: J6.206(DQ38) U22.Y7(D1_MDQ38)
M1_MDQ39: J6.207(DQ39) U22.Y8(D1_MDQ39)
M1_MDQ40: J6.90(DQ40) U22.U11(D1_MDQ40)
M1_MDQ41: J6.91(DQ41) U22.U12(D1_MDQ41)
M1_MDQ42: J6.96(DQ42) U22.Y12(D1_MDQ42)
M1_MDQ43: J6.97(DQ43) U22.Y13(D1_MDQ43)
M1_MDQ44: J6.209(DQ44) U22.U9(D1_MDQ44)
M1_MDQ45: J6.210(DQ45) U22.U10(D1_MDQ45)
M1_MDQ46: J6.215(DQ46) U22.Y10(D1_MDQ46)
M1_MDQ47: J6.216(DQ47) U22.Y11(D1_MDQ47)
M1_MDQ48: J6.99(DQ48) U22.AB7(D1_MDQ48)
M1_MDQ49: J6.100(DQ49) U22.AC7(D1_MDQ49)
M1_MDQ50: J6.105(DQ50) U22.AE6(D1_MDQ50)
M1_MDQ51: J6.106(DQ51) U22.AD7(D1_MDQ51)
M1_MDQ52: J6.218(DQ52) U22.AB5(D1_MDQ52)
M1_MDQ53: J6.219(DQ53) U22.AB6(D1_MDQ53)
M1_MDQ54: J6.224(DQ54) U22.AE5(D1_MDQ54)
M1_MDQ55: J6.225(DQ55) U22.AD6(D1_MDQ55)
M1_MDQ56: J6.108(DQ56) U22.AC9(D1_MDQ56)
M1_MDQ57: J6.109(DQ57) U22.AD9(D1_MDQ57)
M1_MDQ58: J6.114(DQ58) U22.AB13(D1_MDQ58)
M1_MDQ59: J6.115(DQ59) U22.AC13(D1_MDQ59)
M1_MDQ60: J6.227(DQ60) U22.AB9(D1_MDQ60)
M1_MDQ61: J6.228(DQ61) U22.AA9(D1_MDQ61)
M1_MDQ62: J6.233(DQ62) U22.AB12(D1_MDQ62)
M1_MDQ63: J6.234(DQ63) U22.AC12(D1_MDQ63)
M1_MDQS_N0: J6.6(~{DQS0}) U22.F6(~{D1_MDQS00})
M1_MDQS_N1: J6.15(~{DQS1}) U22.H5(~{D1_MDQS01})
M1_MDQS_N2: J6.24(~{DQS2}) U22.N8(~{D1_MDQS02})
M1_MDQS_N3: J6.33(~{DQS3}) U22.N5(~{D1_MDQS03})
M1_MDQS_N4: J6.84(~{DQS4}) U22.W7(~{D1_MDQS04})
M1_MDQS_N5: J6.93(~{DQS5}) U22.W10(~{D1_MDQS05})
M1_MDQS_N6: J6.102(~{DQS6}) U22.AD4(~{D1_MDQS06})
M1_MDQS_N7: J6.111(~{DQS7}) U22.AB11(~{D1_MDQS07})
M1_MDQS_N8: J6.42(~{DQS8}) U22.W5(~{D1_MDQS08})
M1_MDQS_N9: J6.126(~{NC7_DQS9}) U22.D6(~{D1_MDQS09})
M1_MDQS_N10: J6.135(~{NC8_DQS10}) U22.H6(~{D1_MDQS10})
M1_MDQS_N11: J6.144(~{NC9_DQS11}) U22.M7(~{D1_MDQS11})
M1_MDQS_N12: J6.153(~{NC10_DQS12}) U22.M4(~{D1_MDQS12})
M1_MDQS_N13: J6.204(~{NC11_DQS13}) U22.V8(~{D1_MDQS13})
M1_MDQS_N14: J6.213(~{NC12_DQS14}) U22.V11(~{D1_MDQS14})
M1_MDQS_N15: J6.222(~{NC13_DQS15}) U22.AC5(~{D1_MDQS15})
M1_MDQS_N16: J6.231(~{NC14_DQS16}) U22.AC10(~{D1_MDQS16})
M1_MDQS_N17: J6.162(~{NC15_DQS17}) U22.V4(~{D1_MDQS17})
M1_MDQS_P0: J6.7(DQS0_P) U22.F5(D1_MDQS00)
M1_MDQS_P1: J6.16(DQS1_P) U22.G5(D1_MDQS01)
M1_MDQS_P2: J6.25(DQS2_P) U22.N7(D1_MDQS02)
M1_MDQS_P3: J6.34(DQS3_P) U22.N4(D1_MDQS03)
M1_MDQS_P4: J6.85(DQS4_P) U22.W8(D1_MDQS04)
M1_MDQS_P5: J6.94(DQS5_P) U22.W11(D1_MDQS05)
M1_MDQS_P6: J6.103(DQS6_P) U22.AE4(D1_MDQS06)
M1_MDQS_P7: J6.112(DQS7_P) U22.AC11(D1_MDQS07)
M1_MDQS_P8: J6.43(DQS8_P) U22.W4(D1_MDQS08)
M1_MDQS_P9: J6.125(DM0_DQS9_P) U22.D7(D1_MDQS09)
M1_MDQS_P10: J6.134(DM1_DQS10_P) U22.H7(D1_MDQS10)
M1_MDQS_P11: J6.143(DM2_DQS11_P) U22.M8(D1_MDQS11)
M1_MDQS_P12: J6.152(DM3_DQS12_P) U22.M5(D1_MDQS12)
M1_MDQS_P13: J6.203(DM4_DQS13_P) U22.V7(D1_MDQS13)
M1_MDQS_P14: J6.212(DM5_DQS14_P) U22.V10(D1_MDQS14)
M1_MDQS_P15: J6.221(DM6_DQS15_P) U22.AC4(D1_MDQS15)
M1_MDQS_P16: J6.230(DM7_DQS16_P) U22.AB10(D1_MDQS16)
M1_MDQS_P17: J6.161(DM8_DQS17_P) U22.V5(D1_MDQS17)
M1_MECC0: J6.39(CB0) U22.U5(D1_MECC0)
M1_MECC1: J6.40(CB1) U22.U4(D1_MECC1)
M1_MECC2: J6.45(CB2) U22.AA5(D1_MECC2)
M1_MECC3: J6.46(CB3) U22.AA4(D1_MECC3)
M1_MECC4: J6.158(CB4) U22.T5(D1_MECC4)
M1_MECC5: J6.159(CB5) U22.T4(D1_MECC5)
M1_MECC6: J6.164(CB6) U22.Y5(D1_MECC6)
M1_MECC7: J6.165(CB7) U22.Y4(D1_MECC7)
M1_MODT0: J6.195(ODT0) U22.AA1(D1_MODT0)
M1_MODT1: J6.77(ODT1) U22.AE1(D1_MODT1)
M1_MRAS_B: J6.192(RAS_L) U22.V2(~{D1_MRAS})
M1_MWE_B: J6.73(WE_L) U22.W2(~{D1_MWE})
M1_PARERR_B: J6.53(NC17_ERROUT_L) R291.2 U22.A4(~{D1_MAPAR_ERR})
M1_PAROUT: J6.68(NC16_PARIN_L) U22.R1(D1_MAPAR_OUT)
M1_VREF_ISO: C780.1 C781.1 R713.1 U22.V13(D1_MVREF)
M2_MA0: U22.AU1(D2_MA00) ; also on sheet 32
M2_MA1: U22.BC5(D2_MA01) ; also on sheet 32
M2_MA2: U22.BD4(D2_MA02) ; also on sheet 32
M2_MA3: U22.BD5(D2_MA03) ; also on sheet 32
M2_MA4: U22.BC6(D2_MA04) ; also on sheet 32
M2_MA5: U22.BC7(D2_MA05) ; also on sheet 32
M2_MA6: U22.BD7(D2_MA06) ; also on sheet 32
M2_MA7: U22.BC9(D2_MA07) ; also on sheet 32
M2_MA8: U22.BD8(D2_MA08) ; also on sheet 32
M2_MA9: U22.BC10(D2_MA09) ; also on sheet 32
M2_MA10: U22.AT2(D2_MA10) ; also on sheet 32
M2_MA11: U22.BD9(D2_MA11) ; also on sheet 32
M2_MA12: U22.BC11(D2_MA12) ; also on sheet 32
M2_MA13: U22.AK2(D2_MA13) ; also on sheet 32
M2_MA14: U22.BC13(D2_MA14) ; also on sheet 32
M2_MA15: U22.BC14(D2_MA15) ; also on sheet 32
M2_MBA0: U22.AR2(D2_MBA0) ; also on sheet 32
M2_MBA1: U22.AT1(D2_MBA1) ; also on sheet 32
M2_MBA2: U22.BD12(D2_MBA2) ; also on sheet 32
M2_MCAS_B: U22.AM2(~{D2_MCAS}) ; also on sheet 32
M2_MCKE0: U22.BD15(D2_MCKE0) ; also on sheet 32
M2_MCKE1: U22.BD16(D2_MCKE1) ; also on sheet 32
M2_MCLK0_N: U22.AY1(~{D2_MCK0}) ; also on sheet 32
M2_MCLK0_P: U22.BA1(D2_MCK0) ; also on sheet 32
M2_MCLK1_N: U22.BB2(~{D2_MCK1}) ; also on sheet 32
M2_MCLK1_P: U22.BB1(D2_MCK1) ; also on sheet 32
M2_MCLK2_N: R213.2 U22.AW2(~{D2_MCK2})
M2_MCLK2_P: R211.2 U22.AY2(D2_MCK2)
M2_MCLK3_N: R199.2 U22.BC3(~{D2_MCK3})
M2_MCLK3_P: R200.2 U22.BC2(D2_MCK3)
M2_MCS_B0: U22.AP2(~{D2_MCS0}) ; also on sheet 32
M2_MCS_B1: U22.AH2(~{D2_MCS1}) ; also on sheet 32
M2_MCS_B2: U22.AN1(~{D2_MCS2}) ; also on sheet 32
M2_MCS_B3: U22.AJ1(~{D2_MCS3}) ; also on sheet 32
M2_MDIC_0: R218.1 U22.AV2(D2_MDIC0)
M2_MDIC_1: R198.1 U22.BD3(D2_MDIC1)
M2_MDQ0: U22.AY15(D2_MDQ00) ; also on sheet 32
M2_MDQ1: U22.BA15(D2_MDQ01) ; also on sheet 32
M2_MDQ2: U22.AY11(D2_MDQ02) ; also on sheet 32
M2_MDQ3: U22.BA11(D2_MDQ03) ; also on sheet 32
M2_MDQ4: U22.AY16(D2_MDQ04) ; also on sheet 32
M2_MDQ5: U22.BA16(D2_MDQ05) ; also on sheet 32
M2_MDQ6: U22.AY12(D2_MDQ06) ; also on sheet 32
M2_MDQ7: U22.BA12(D2_MDQ07) ; also on sheet 32
M2_MDQ8: U22.AU15(D2_MDQ08) ; also on sheet 32
M2_MDQ9: U22.AV15(D2_MDQ09) ; also on sheet 32
M2_MDQ10: U22.AU11(D2_MDQ10) ; also on sheet 32
M2_MDQ11: U22.AV11(D2_MDQ11) ; also on sheet 32
M2_MDQ12: U22.AU16(D2_MDQ12) ; also on sheet 32
M2_MDQ13: U22.AV16(D2_MDQ13) ; also on sheet 32
M2_MDQ14: U22.AU12(D2_MDQ14) ; also on sheet 32
M2_MDQ15: U22.AV12(D2_MDQ15) ; also on sheet 32
M2_MDQ16: U22.AU8(D2_MDQ16) ; also on sheet 32
M2_MDQ17: U22.AV8(D2_MDQ17) ; also on sheet 32
M2_MDQ18: U22.AU4(D2_MDQ18) ; also on sheet 32
M2_MDQ19: U22.AV4(D2_MDQ19) ; also on sheet 32
M2_MDQ20: U22.AU9(D2_MDQ20) ; also on sheet 32
M2_MDQ21: U22.AV9(D2_MDQ21) ; also on sheet 32
M2_MDQ22: U22.AU5(D2_MDQ22) ; also on sheet 32
M2_MDQ23: U22.AV5(D2_MDQ23) ; also on sheet 32
M2_MDQ24: U22.AY8(D2_MDQ24) ; also on sheet 32
M2_MDQ25: U22.BA8(D2_MDQ25) ; also on sheet 32
M2_MDQ26: U22.AY4(D2_MDQ26) ; also on sheet 32
M2_MDQ27: U22.BA4(D2_MDQ27) ; also on sheet 32
M2_MDQ28: U22.AY9(D2_MDQ28) ; also on sheet 32
M2_MDQ29: U22.BA9(D2_MDQ29) ; also on sheet 32
M2_MDQ30: U22.AY5(D2_MDQ30) ; also on sheet 32
M2_MDQ31: U22.BA5(D2_MDQ31) ; also on sheet 32
M2_MDQ32: U22.AP8(D2_MDQ32) ; also on sheet 32
M2_MDQ33: U22.AP7(D2_MDQ33) ; also on sheet 32
M2_MDQ34: U22.AK8(D2_MDQ34) ; also on sheet 32
M2_MDQ35: U22.AK7(D2_MDQ35) ; also on sheet 32
M2_MDQ36: U22.AR8(D2_MDQ36) ; also on sheet 32
M2_MDQ37: U22.AR7(D2_MDQ37) ; also on sheet 32
M2_MDQ38: U22.AL8(D2_MDQ38) ; also on sheet 32
M2_MDQ39: U22.AL7(D2_MDQ39) ; also on sheet 32
M2_MDQ40: U22.AP4(D2_MDQ40) ; also on sheet 32
M2_MDQ41: U22.AP5(D2_MDQ41) ; also on sheet 32
M2_MDQ42: U22.AK4(D2_MDQ42) ; also on sheet 32
M2_MDQ43: U22.AK5(D2_MDQ43) ; also on sheet 32
M2_MDQ44: U22.AR4(D2_MDQ44) ; also on sheet 32
M2_MDQ45: U22.AR5(D2_MDQ45) ; also on sheet 32
M2_MDQ46: U22.AL4(D2_MDQ46) ; also on sheet 32
M2_MDQ47: U22.AL5(D2_MDQ47) ; also on sheet 32
M2_MDQ48: U22.AH6(D2_MDQ48) ; also on sheet 32
M2_MDQ49: U22.AH5(D2_MDQ49) ; also on sheet 32
M2_MDQ50: U22.AF8(D2_MDQ50) ; also on sheet 32
M2_MDQ51: U22.AE8(D2_MDQ51) ; also on sheet 32
M2_MDQ52: U22.AH8(D2_MDQ52) ; also on sheet 32
M2_MDQ53: U22.AH7(D2_MDQ53) ; also on sheet 32
M2_MDQ54: U22.AF7(D2_MDQ54) ; also on sheet 32
M2_MDQ55: U22.AG7(D2_MDQ55) ; also on sheet 32
M2_MDQ56: U22.AG9(D2_MDQ56) ; also on sheet 32
M2_MDQ57: U22.AG10(D2_MDQ57) ; also on sheet 32
M2_MDQ58: U22.AF13(D2_MDQ58) ; also on sheet 32
M2_MDQ59: U22.AE13(D2_MDQ59) ; also on sheet 32
M2_MDQ60: U22.AH10(D2_MDQ60) ; also on sheet 32
M2_MDQ61: U22.AH11(D2_MDQ61) ; also on sheet 32
M2_MDQ62: U22.AF12(D2_MDQ62) ; also on sheet 32
M2_MDQ63: U22.AE12(D2_MDQ63) ; also on sheet 32
M2_MDQS_N0: U22.AY13(~{D2_MDQS00}) ; also on sheet 32
M2_MDQS_N1: U22.AU13(~{D2_MDQS01}) ; also on sheet 32
M2_MDQS_N2: U22.AU6(~{D2_MDQS02}) ; also on sheet 32
M2_MDQS_N3: U22.AY6(~{D2_MDQS03}) ; also on sheet 32
M2_MDQS_N4: U22.AM8(~{D2_MDQS04}) ; also on sheet 32
M2_MDQS_N5: U22.AM4(~{D2_MDQS05}) ; also on sheet 32
M2_MDQS_N6: U22.AG5(~{D2_MDQS06}) ; also on sheet 32
M2_MDQS_N7: U22.AE10(~{D2_MDQS07}) ; also on sheet 32
M2_MDQS_N8: U22.AM11(~{D2_MDQS08}) ; also on sheet 32
M2_MDQS_N9: U22.BA14(~{D2_MDQS09}) ; also on sheet 32
M2_MDQS_N10: U22.AV14(~{D2_MDQS10}) ; also on sheet 32
M2_MDQS_N11: U22.AV7(~{D2_MDQS11}) ; also on sheet 32
M2_MDQS_N12: U22.BA7(~{D2_MDQS12}) ; also on sheet 32
M2_MDQS_N13: U22.AN7(~{D2_MDQS13}) ; also on sheet 32
M2_MDQS_N14: U22.AN5(~{D2_MDQS14}) ; also on sheet 32
M2_MDQS_N15: U22.AG4(~{D2_MDQS15}) ; also on sheet 32
M2_MDQS_N16: U22.AF11(~{D2_MDQS16}) ; also on sheet 32
M2_MDQS_N17: U22.AN10(~{D2_MDQS17}) ; also on sheet 32
M2_MDQS_P0: U22.BA13(D2_MDQS00) ; also on sheet 32
M2_MDQS_P1: U22.AV13(D2_MDQS01) ; also on sheet 32
M2_MDQS_P2: U22.AV6(D2_MDQS02) ; also on sheet 32
M2_MDQS_P3: U22.BA6(D2_MDQS03) ; also on sheet 32
M2_MDQS_P4: U22.AM7(D2_MDQS04) ; also on sheet 32
M2_MDQS_P5: U22.AM5(D2_MDQS05) ; also on sheet 32
M2_MDQS_P6: U22.AG6(D2_MDQS06) ; also on sheet 32
M2_MDQS_P7: U22.AE11(D2_MDQS07) ; also on sheet 32
M2_MDQS_P8: U22.AM10(D2_MDQS08) ; also on sheet 32
M2_MDQS_P9: U22.AY14(D2_MDQS09) ; also on sheet 32
M2_MDQS_P10: U22.AU14(D2_MDQS10) ; also on sheet 32
M2_MDQS_P11: U22.AU7(D2_MDQS11) ; also on sheet 32
M2_MDQS_P12: U22.AY7(D2_MDQS12) ; also on sheet 32
M2_MDQS_P13: U22.AN8(D2_MDQS13) ; also on sheet 32
M2_MDQS_P14: U22.AN4(D2_MDQS14) ; also on sheet 32
M2_MDQS_P15: U22.AH4(D2_MDQS15) ; also on sheet 32
M2_MDQS_P16: U22.AF10(D2_MDQS16) ; also on sheet 32
M2_MDQS_P17: U22.AN11(D2_MDQS17) ; also on sheet 32
M2_MECC0: U22.AP11(D2_MECC0) ; also on sheet 32
M2_MECC1: U22.AP10(D2_MECC1) ; also on sheet 32
M2_MECC2: U22.AK11(D2_MECC2) ; also on sheet 32
M2_MECC3: U22.AK10(D2_MECC3) ; also on sheet 32
M2_MECC4: U22.AR11(D2_MECC4) ; also on sheet 32
M2_MECC5: U22.AR10(D2_MECC5) ; also on sheet 32
M2_MECC6: U22.AL11(D2_MECC6) ; also on sheet 32
M2_MECC7: U22.AL10(D2_MECC7) ; also on sheet 32
M2_MODT0: U22.AL2(D2_MODT0) ; also on sheet 32
M2_MODT1: U22.AG2(D2_MODT1) ; also on sheet 32
M2_MRAS_B: U22.AP1(~{D2_MRAS}) ; also on sheet 32
M2_MWE_B: U22.AM1(~{D2_MWE}) ; also on sheet 32
M2_PARERR_B: R197.2 U22.BD11(~{D2_MAPAR_ERR}) ; also on sheet 32
M2_PAROUT: U22.AV1(D2_MAPAR_OUT) ; also on sheet 32
M2_VREF_ISO: C656.1 C679.1 R703.1 U22.AH13(D2_MVREF)
M3_MA0: U22.AL44(D3_MA00) ; also on sheet 33
M3_MA1: U22.AW43(D3_MA01) ; also on sheet 33
M3_MA2: U22.AW44(D3_MA02) ; also on sheet 33
M3_MA3: U22.AY43(D3_MA03) ; also on sheet 33
M3_MA4: U22.BA43(D3_MA04) ; also on sheet 33
M3_MA5: U22.BA44(D3_MA05) ; also on sheet 33
M3_MA6: U22.BB44(D3_MA06) ; also on sheet 33
M3_MA7: U22.BC43(D3_MA07) ; also on sheet 33
M3_MA8: U22.BC42(D3_MA08) ; also on sheet 33
M3_MA9: U22.BD41(D3_MA09) ; also on sheet 33
M3_MA10: U22.AK44(D3_MA10) ; also on sheet 33
M3_MA11: U22.BD42(D3_MA11) ; also on sheet 33
M3_MA12: U22.BC40(D3_MA12) ; also on sheet 33
M3_MA13: U22.AB44(D3_MA13) ; also on sheet 33
M3_MA14: U22.BC39(D3_MA14) ; also on sheet 33
M3_MA15: U22.BD38(D3_MA15) ; also on sheet 33
M3_MBA0: U22.AJ43(D3_MBA0) ; also on sheet 33
M3_MBA1: U22.AJ44(D3_MBA1) ; also on sheet 33
M3_MBA2: U22.BC38(D3_MBA2) ; also on sheet 33
M3_MCAS_B: U22.AE44(~{D3_MCAS}) ; also on sheet 33
M3_MCKE0: U22.BD37(D3_MCKE0) ; also on sheet 33
M3_MCKE1: U22.BC35(D3_MCKE1) ; also on sheet 33
M3_MCLK0_N: U22.AR43(~{D3_MCK0}) ; also on sheet 33
M3_MCLK0_P: U22.AT43(D3_MCK0) ; also on sheet 33
M3_MCLK1_N: U22.AP44(~{D3_MCK1}) ; also on sheet 33
M3_MCLK1_P: U22.AR44(D3_MCK1) ; also on sheet 33
M3_MCLK2_N: R229.2 U22.AN43(~{D3_MCK2})
M3_MCLK2_P: R230.2 U22.AN44(D3_MCK2)
M3_MCLK3_N: R221.2 U22.AU43(~{D3_MCK3})
M3_MCLK3_P: R224.2 U22.AU44(D3_MCK3)
M3_MCS_B0: U22.AF44(~{D3_MCS0}) ; also on sheet 33
M3_MCS_B1: U22.AC44(~{D3_MCS1}) ; also on sheet 33
M3_MCS_B2: U22.AG43(~{D3_MCS2}) ; also on sheet 33
M3_MCS_B3: U22.AC43(~{D3_MCS3}) ; also on sheet 33
M3_MDIC_0: R232.1 U22.AM43(D3_MDIC0)
M3_MDIC_1: R219.1 U22.AV44(D3_MDIC1)
M3_MDQ0: U22.AY35(D3_MDQ00) ; also on sheet 33
M3_MDQ1: U22.BA35(D3_MDQ01) ; also on sheet 33
M3_MDQ2: U22.AW37(D3_MDQ02) ; also on sheet 33
M3_MDQ3: U22.AV37(D3_MDQ03) ; also on sheet 33
M3_MDQ4: U22.AU35(D3_MDQ04) ; also on sheet 33
M3_MDQ5: U22.AV35(D3_MDQ05) ; also on sheet 33
M3_MDQ6: U22.BA37(D3_MDQ06) ; also on sheet 33
M3_MDQ7: U22.AY37(D3_MDQ07) ; also on sheet 33
M3_MDQ8: U22.AP35(D3_MDQ08) ; also on sheet 33
M3_MDQ9: U22.AR35(D3_MDQ09) ; also on sheet 33
M3_MDQ10: U22.AR38(D3_MDQ10) ; also on sheet 33
M3_MDQ11: U22.AP38(D3_MDQ11) ; also on sheet 33
M3_MDQ12: U22.AP34(D3_MDQ12) ; also on sheet 33
M3_MDQ13: U22.AR34(D3_MDQ13) ; also on sheet 33
M3_MDQ14: U22.AT38(D3_MDQ14) ; also on sheet 33
M3_MDQ15: U22.AU38(D3_MDQ15) ; also on sheet 33
M3_MDQ16: U22.BA40(D3_MDQ16) ; also on sheet 33
M3_MDQ17: U22.AY40(D3_MDQ17) ; also on sheet 33
M3_MDQ18: U22.AV40(D3_MDQ18) ; also on sheet 33
M3_MDQ19: U22.AU40(D3_MDQ19) ; also on sheet 33
M3_MDQ20: U22.BA39(D3_MDQ20) ; also on sheet 33
M3_MDQ21: U22.AY39(D3_MDQ21) ; also on sheet 33
M3_MDQ22: U22.AW41(D3_MDQ22) ; also on sheet 33
M3_MDQ23: U22.AV41(D3_MDQ23) ; also on sheet 33
M3_MDQ24: U22.AR40(D3_MDQ24) ; also on sheet 33
M3_MDQ25: U22.AR41(D3_MDQ25) ; also on sheet 33
M3_MDQ26: U22.AL40(D3_MDQ26) ; also on sheet 33
M3_MDQ27: U22.AL41(D3_MDQ27) ; also on sheet 33
M3_MDQ28: U22.AT40(D3_MDQ28) ; also on sheet 33
M3_MDQ29: U22.AT41(D3_MDQ29) ; also on sheet 33
M3_MDQ30: U22.AM40(D3_MDQ30) ; also on sheet 33
M3_MDQ31: U22.AM41(D3_MDQ31) ; also on sheet 33
M3_MDQ32: U22.AH40(D3_MDQ32) ; also on sheet 33
M3_MDQ33: U22.AH41(D3_MDQ33) ; also on sheet 33
M3_MDQ34: U22.AD40(D3_MDQ34) ; also on sheet 33
M3_MDQ35: U22.AD41(D3_MDQ35) ; also on sheet 33
M3_MDQ36: U22.AJ40(D3_MDQ36) ; also on sheet 33
M3_MDQ37: U22.AJ41(D3_MDQ37) ; also on sheet 33
M3_MDQ38: U22.AE40(D3_MDQ38) ; also on sheet 33
M3_MDQ39: U22.AE41(D3_MDQ39) ; also on sheet 33
M3_MDQ40: U22.AH38(D3_MDQ40) ; also on sheet 33
M3_MDQ41: U22.AH37(D3_MDQ41) ; also on sheet 33
M3_MDQ42: U22.AD38(D3_MDQ42) ; also on sheet 33
M3_MDQ43: U22.AD37(D3_MDQ43) ; also on sheet 33
M3_MDQ44: U22.AJ38(D3_MDQ44) ; also on sheet 33
M3_MDQ45: U22.AJ37(D3_MDQ45) ; also on sheet 33
M3_MDQ46: U22.AE38(D3_MDQ46) ; also on sheet 33
M3_MDQ47: U22.AE37(D3_MDQ47) ; also on sheet 33
M3_MDQ48: U22.AG35(D3_MDQ48) ; also on sheet 33
M3_MDQ49: U22.AG34(D3_MDQ49) ; also on sheet 33
M3_MDQ50: U22.AC35(D3_MDQ50) ; also on sheet 33
M3_MDQ51: U22.AC34(D3_MDQ51) ; also on sheet 33
M3_MDQ52: U22.AH35(D3_MDQ52) ; also on sheet 33
M3_MDQ53: U22.AH34(D3_MDQ53) ; also on sheet 33
M3_MDQ54: U22.AD35(D3_MDQ54) ; also on sheet 33
M3_MDQ55: U22.AD34(D3_MDQ55) ; also on sheet 33
M3_MDQ56: U22.AB40(D3_MDQ56) ; also on sheet 33
M3_MDQ57: U22.AA40(D3_MDQ57) ; also on sheet 33
M3_MDQ58: U22.AB36(D3_MDQ58) ; also on sheet 33
M3_MDQ59: U22.AA36(D3_MDQ59) ; also on sheet 33
M3_MDQ60: U22.AB41(D3_MDQ60) ; also on sheet 33
M3_MDQ61: U22.AA41(D3_MDQ61) ; also on sheet 33
M3_MDQ62: U22.AB37(D3_MDQ62) ; also on sheet 33
M3_MDQ63: U22.AA37(D3_MDQ63) ; also on sheet 33
M3_MDQS_N0: U22.BA36(~{D3_MDQS00}) ; also on sheet 33
M3_MDQS_N1: U22.AR37(~{D3_MDQS01}) ; also on sheet 33
M3_MDQS_N2: U22.AW39(~{D3_MDQS02}) ; also on sheet 33
M3_MDQS_N3: U22.AN40(~{D3_MDQS03}) ; also on sheet 33
M3_MDQS_N4: U22.AF40(~{D3_MDQS04}) ; also on sheet 33
M3_MDQS_N5: U22.AF38(~{D3_MDQS05}) ; also on sheet 33
M3_MDQS_N6: U22.AE35(~{D3_MDQS06}) ; also on sheet 33
M3_MDQS_N7: U22.AB38(~{D3_MDQS07}) ; also on sheet 33
M3_MDQS_N8: U22.AL37(~{D3_MDQS08}) ; also on sheet 33
M3_MDQS_N9: U22.AV36(~{D3_MDQS09}) ; also on sheet 33
M3_MDQS_N10: U22.AR36(~{D3_MDQS10}) ; also on sheet 33
M3_MDQS_N11: U22.AY41(~{D3_MDQS11}) ; also on sheet 33
M3_MDQS_N12: U22.AP41(~{D3_MDQS12}) ; also on sheet 33
M3_MDQS_N13: U22.AG41(~{D3_MDQS13}) ; also on sheet 33
M3_MDQS_N14: U22.AG37(~{D3_MDQS14}) ; also on sheet 33
M3_MDQS_N15: U22.AF34(~{D3_MDQS15}) ; also on sheet 33
M3_MDQS_N16: U22.AA39(~{D3_MDQS16}) ; also on sheet 33
M3_MDQS_N17: U22.AM38(~{D3_MDQS17}) ; also on sheet 33
M3_MDQS_P0: U22.AY36(D3_MDQS00) ; also on sheet 33
M3_MDQS_P1: U22.AT37(D3_MDQS01) ; also on sheet 33
M3_MDQS_P2: U22.AV39(D3_MDQS02) ; also on sheet 33
M3_MDQS_P3: U22.AN41(D3_MDQS03) ; also on sheet 33
M3_MDQS_P4: U22.AF41(D3_MDQS04) ; also on sheet 33
M3_MDQS_P5: U22.AF37(D3_MDQS05) ; also on sheet 33
M3_MDQS_P6: U22.AE34(D3_MDQS06) ; also on sheet 33
M3_MDQS_P7: U22.AA38(D3_MDQS07) ; also on sheet 33
M3_MDQS_P8: U22.AL38(D3_MDQS08) ; also on sheet 33
M3_MDQS_P9: U22.AU36(D3_MDQS09) ; also on sheet 33
M3_MDQS_P10: U22.AP36(D3_MDQS10) ; also on sheet 33
M3_MDQS_P11: U22.BA41(D3_MDQS11) ; also on sheet 33
M3_MDQS_P12: U22.AP40(D3_MDQS12) ; also on sheet 33
M3_MDQS_P13: U22.AG40(D3_MDQS13) ; also on sheet 33
M3_MDQS_P14: U22.AG38(D3_MDQS14) ; also on sheet 33
M3_MDQS_P15: U22.AF35(D3_MDQS15) ; also on sheet 33
M3_MDQS_P16: U22.AB39(D3_MDQS16) ; also on sheet 33
M3_MDQS_P17: U22.AM37(D3_MDQS17) ; also on sheet 33
M3_MECC0: U22.AN37(D3_MECC0) ; also on sheet 33
M3_MECC1: U22.AN38(D3_MECC1) ; also on sheet 33
M3_MECC2: U22.AK35(D3_MECC2) ; also on sheet 33
M3_MECC3: U22.AK34(D3_MECC3) ; also on sheet 33
M3_MECC4: U22.AM34(D3_MECC4) ; also on sheet 33
M3_MECC5: U22.AM35(D3_MECC5) ; also on sheet 33
M3_MECC6: U22.AL36(D3_MECC6) ; also on sheet 33
M3_MECC7: U22.AL35(D3_MECC7) ; also on sheet 33
M3_MODT0: U22.AE43(D3_MODT0) ; also on sheet 33
M3_MODT1: U22.AA43(D3_MODT1) ; also on sheet 33
M3_MRAS_B: U22.AH43(~{D3_MRAS}) ; also on sheet 33
M3_MWE_B: U22.AG44(~{D3_MWE}) ; also on sheet 33
M3_PARERR_B: R202.2 U22.BD40(~{D3_MAPAR_ERR}) ; also on sheet 33
M3_PAROUT: U22.AL43(D3_MAPAR_OUT) ; also on sheet 33
M3_VREF_ISO: C703.1 C704.1 R705.1 U22.AD32(D3_MVREF)
M_VREF_A: C152.1 C304.1 J6.1(VREFDQ) J6.67(VREFCA) R703.2 R713.2 ; also on sheet 13 32
M_VREF_B: R705.2 ; also on sheet 13 33
M_VTT_A: C28.1 C199.1 C215.1 J6.48(NC3_VTT3) J6.49(NC4_VTT4) J6.120(VTT1) J6.240(VTT2) ; also on sheet 13 32
RST_MEM_B: J6.168(RESET_L) ; also on sheet 8 32 33

Not connected (* = marked no-connect by the designer): J6 167(NC19_TEST)* 187(NC18_EVENT_L)*; U22 A8(D1_MCKE3)* AA44(D3_MODT3)* AB2(D1_MODT2)* AD43(D3_MODT2)* AE2(D1_MODT3)* AH1(D2_MODT3)* AK1(D2_MODT2)* B7(D1_MCKE2)* BC15(D2_MCKE3)* BC36(D3_MCKE2)* BD13(D2_MCKE2)* BD36(D3_MCKE3)*

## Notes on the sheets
sheet 28
- T4240 DDR Port #1
- i
- Route as 18-lane differential pair
sheet 29
- T4240 DDR Port #2
- i
- Route as 18-lane differential pair
sheet 30
- T4240 DDR Port #3
- i
- Route as 18-lane differential pair
sheet 31
- DDR3 DIMM #1
- SPD ADDR = 0x52
